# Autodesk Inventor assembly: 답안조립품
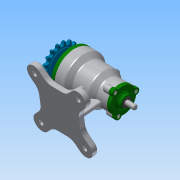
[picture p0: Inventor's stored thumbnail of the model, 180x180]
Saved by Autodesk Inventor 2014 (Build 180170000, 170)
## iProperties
Created: 2017-03
Part Number: 답안조립품
Document SubType Name: Assembly
Designer: 00
Author: 00
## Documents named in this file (14)
- C:\Users\00\Desktop\470307V1001\답안조립품.iam
- C:\Users\00\Desktop\470307V1001\1.본체.ipt
- C:\Users\00\Desktop\470307V1001\뒤커버.ipt
- C:\Users\00\Desktop\470307V1001\베어링-6200.ipt
- C:\Users\00\Desktop\470307V1001\베어링-6203.ipt
- C:\Users\00\Desktop\470307V1001\볼트 M4 x 12.ipt
- C:\Users\00\Desktop\470307V1001\볼트 M5 x 10.ipt
- 볼트 M5 x 10.ipt
- C:\Users\00\Desktop\470307V1001\스프로킷.ipt
- C:\Users\00\Desktop\470307V1001\앞커버.ipt
- C:\Users\00\Desktop\470307V1001\오일 실 10 20 7.ipt
- C:\Users\00\Desktop\470307V1001\오일 실 17 30 8.ipt
- C:\Users\00\Desktop\470307V1001\축.ipt
- C:\Users\00\Desktop\470307V1001\키5x5.ipt
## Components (10 placed, 2 different names)
1. 1.본체:1
2. ISO 4762 M4 x 12:1
3. ISO 4762 M4 x 12:3
4. ISO 4762 M4 x 12:4
5. ISO 4762 M4 x 12:5
6. ISO 4762 M4 x 12:6
7. ISO 4762 M4 x 12:7
8. ISO 4762 M4 x 12:2
9. ISO 4762 M4 x 12:8
10. ISO 4762 M4 x 12:9
